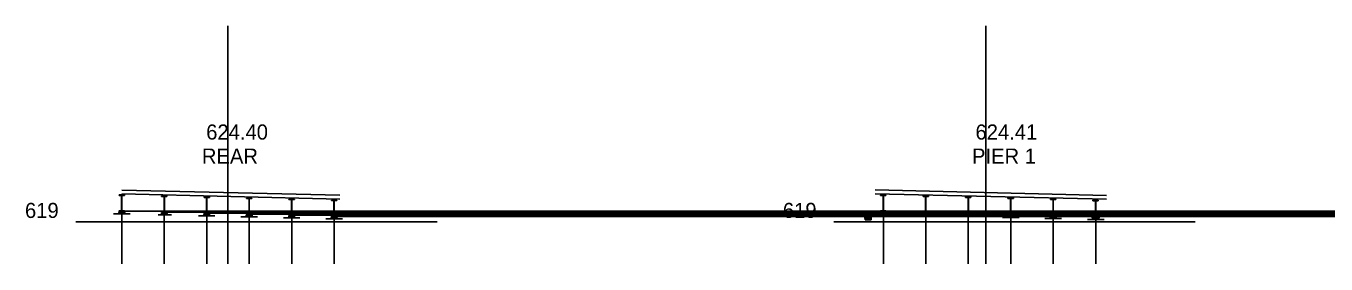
# Model space of a CAD drawing. Extents: x 2376379 to 2383101, y 559608 to 561720.
# Drawn here: x 2377257.5 to 2377498.6, y 560758 to 560802.1 of the extents above; entities that cross this region are included whole.
import ezdxf

# ---------------------------------------------------------------- set-up
doc = ezdxf.new("R2010")
doc.units = 0
for name, color, linetype in [('BR_X_SV_Abut', 7, 'Continuous'), ('DR_X_Ditch', 7, 'Continuous'), ('SV_X_Toe_of_Slope', 7, 'Continuous')]:
    doc.layers.add(name, color=color, linetype=linetype)

msp = doc.modelspace()

# ---------------------------------------------------------------- linework, layer by layer
at = {"layer": 'BR_X_SV_Abut'}
for p, q in [((2377413.12, 560766.61), (2377413.12, 560766.41)), ((2377414.29, 560766.61), (2377413.12, 560766.61)), ((2377414.29, 560766.41), (2377413.12, 560766.41)), ((2377413.16, 560766.41), (2377413.16, 560766.12)), ((2377414.25, 560766.12), (2377413.16, 560766.12)), ((2377414.25, 560766.41), (2377414.25, 560766.12)), ((2377414.29, 560766.61), (2377414.29, 560766.41))]:
    msp.add_line(p, q, dxfattribs=at)
at = {"layer": 'DR_X_Ditch'}
for p, q in [((2377274.81, 560770.75), (2377275.81, 560770.75)), ((2377274.81, 560770.75), (2377274.81, 560770.66)), ((2377274.81, 560770.66), (2377275.81, 560770.66)), ((2377275.28, 560767.83), (2377275.28, 560770.66)), ((2377275.33, 560767.83), (2377275.33, 560770.66)), ((2377275.81, 560770.75), (2377275.81, 560770.66)), ((2377282.69, 560770.56), (2377283.69, 560770.56)), ((2377282.69, 560770.56), (2377282.69, 560770.47)), ((2377282.69, 560770.47), (2377283.69, 560770.47)), ((2377283.16, 560767.64), (2377283.16, 560770.47)), ((2377283.21, 560767.64), (2377283.21, 560770.47)), ((2377283.69, 560770.56), (2377283.69, 560770.47)), ((2377290.56, 560770.38), (2377291.56, 560770.38)), ((2377290.56, 560770.38), (2377290.56, 560770.29)), ((2377290.56, 560770.29), (2377291.56, 560770.29)), ((2377291.03, 560767.46), (2377291.03, 560770.29)), ((2377291.08, 560767.46), (2377291.08, 560770.29)), ((2377291.56, 560770.38), (2377291.56, 560770.29)), ((2377298.43, 560770.16), (2377299.43, 560770.16)), ((2377298.43, 560770.16), (2377298.43, 560770.07)), ((2377299.43, 560770.16), (2377299.43, 560770.07)), ((2377416.01, 560770.74), (2377417.01, 560770.74)), ((2377416.01, 560770.74), (2377416.01, 560770.65)), ((2377416.01, 560770.74), (2377417.01, 560770.74)), ((2377416.01, 560770.65), (2377417.01, 560770.65)), ((2377416.08, 560770.77), (2377416.95, 560770.77)), ((2377416.08, 560770.77), (2377416.08, 560770.74)), ((2377416.49, 560767.82), (2377416.49, 560770.65)), ((2377416.54, 560767.82), (2377416.54, 560770.65)), ((2377416.95, 560770.77), (2377416.95, 560770.74)), ((2377417.01, 560770.74), (2377417.01, 560770.65)), ((2377423.89, 560770.57), (2377424.89, 560770.57)), ((2377423.89, 560770.57), (2377423.89, 560770.48)), ((2377423.89, 560770.57), (2377424.89, 560770.57)), ((2377423.89, 560770.48), (2377424.89, 560770.48)), ((2377423.96, 560770.6), (2377424.83, 560770.6)), ((2377423.96, 560770.6), (2377423.96, 560770.57)), ((2377424.37, 560767.65), (2377424.37, 560770.48)), ((2377424.42, 560767.65), (2377424.42, 560770.48)), ((2377424.83, 560770.6), (2377424.83, 560770.57)), ((2377424.89, 560770.57), (2377424.89, 560770.48)), ((2377431.76, 560770.39), (2377432.76, 560770.39)), ((2377431.76, 560770.39), (2377431.76, 560770.3)), ((2377431.76, 560770.39), (2377432.76, 560770.39)), ((2377431.76, 560770.3), (2377432.76, 560770.3)), ((2377431.83, 560770.42), (2377432.7, 560770.42)), ((2377431.83, 560770.42), (2377431.83, 560770.39)), ((2377432.24, 560767.47), (2377432.24, 560770.3)), ((2377432.29, 560767.47), (2377432.29, 560770.3)), ((2377432.7, 560770.42), (2377432.7, 560770.39)), ((2377432.76, 560770.39), (2377432.76, 560770.3)), ((2377439.64, 560770.19), (2377440.64, 560770.19)), ((2377439.64, 560770.19), (2377439.64, 560770.1)), ((2377439.64, 560770.19), (2377440.64, 560770.19)), ((2377439.71, 560770.22), (2377440.58, 560770.22)), ((2377439.71, 560770.22), (2377439.71, 560770.19)), ((2377440.58, 560770.22), (2377440.58, 560770.19)), ((2377440.64, 560770.19), (2377440.64, 560770.1)), ((2377274.81, 560767.83), (2377275.81, 560767.83)), ((2377274.81, 560767.83), (2377274.81, 560767.75)), ((2377274.81, 560767.75), (2377275.81, 560767.75)), ((2377275.81, 560767.75), (2377275.81, 560767.83)), ((2377298.43, 560770.07), (2377299.43, 560770.07)), ((2377298.9, 560767.24), (2377298.9, 560770.07)), ((2377298.95, 560767.24), (2377298.95, 560770.07)), ((2377306.31, 560770), (2377307.31, 560770)), ((2377306.31, 560770), (2377306.31, 560769.91)), ((2377306.31, 560769.91), (2377307.31, 560769.91)), ((2377306.78, 560767.08), (2377306.78, 560769.91)), ((2377306.83, 560767.08), (2377306.83, 560769.91)), ((2377307.31, 560770), (2377307.31, 560769.91)), ((2377314.18, 560769.8), (2377315.18, 560769.8)), ((2377314.18, 560769.8), (2377314.18, 560769.71)), ((2377314.18, 560769.71), (2377315.18, 560769.71)), ((2377314.65, 560766.88), (2377314.65, 560769.71)), ((2377314.7, 560766.88), (2377314.7, 560769.71)), ((2377315.18, 560769.8), (2377315.18, 560769.71)), ((2377415.95, 560767.74), (2377416.01, 560767.74)), ((2377415.95, 560767.74), (2377415.95, 560767.65)), ((2377416.01, 560767.82), (2377417.01, 560767.82)), ((2377416.01, 560767.82), (2377416.01, 560767.74)), ((2377416.01, 560767.74), (2377417.01, 560767.74)), ((2377417.01, 560767.74), (2377417.01, 560767.82)), ((2377417.01, 560767.74), (2377417.08, 560767.74)), ((2377417.08, 560767.74), (2377417.08, 560767.65)), ((2377439.64, 560770.1), (2377440.64, 560770.1)), ((2377440.12, 560767.27), (2377440.12, 560770.1)), ((2377440.17, 560767.27), (2377440.17, 560770.1)), ((2377447.51, 560769.99), (2377448.51, 560769.99)), ((2377447.51, 560769.99), (2377447.51, 560769.9)), ((2377447.51, 560769.99), (2377448.51, 560769.99)), ((2377447.51, 560769.9), (2377448.51, 560769.9)), ((2377447.58, 560770.02), (2377448.45, 560770.02)), ((2377447.58, 560770.02), (2377447.58, 560769.99)), ((2377447.99, 560767.07), (2377447.99, 560769.9)), ((2377448.04, 560767.07), (2377448.04, 560769.9)), ((2377448.45, 560770.02), (2377448.45, 560769.99)), ((2377448.51, 560769.99), (2377448.51, 560769.9)), ((2377455.39, 560769.77), (2377456.39, 560769.77)), ((2377455.39, 560769.77), (2377455.39, 560769.68)), ((2377455.39, 560769.77), (2377456.39, 560769.77)), ((2377455.39, 560769.68), (2377456.39, 560769.68)), ((2377455.46, 560769.8), (2377456.33, 560769.8)), ((2377455.46, 560769.8), (2377455.46, 560769.77)), ((2377455.87, 560766.85), (2377455.87, 560769.68)), ((2377455.92, 560766.85), (2377455.92, 560769.68)), ((2377456.33, 560769.8), (2377456.33, 560769.77)), ((2377456.39, 560769.77), (2377456.39, 560769.68)), ((2377282.69, 560767.64), (2377283.69, 560767.64)), ((2377282.69, 560767.64), (2377282.69, 560767.56)), ((2377282.69, 560767.56), (2377283.69, 560767.56)), ((2377283.69, 560767.56), (2377283.69, 560767.64)), ((2377290.56, 560767.46), (2377291.56, 560767.46)), ((2377290.56, 560767.46), (2377290.56, 560767.38)), ((2377290.56, 560767.38), (2377291.56, 560767.38)), ((2377291.56, 560767.38), (2377291.56, 560767.46)), ((2377298.43, 560767.24), (2377299.43, 560767.24)), ((2377298.43, 560767.24), (2377298.43, 560767.16)), ((2377298.43, 560767.16), (2377299.43, 560767.16)), ((2377299.43, 560767.16), (2377299.43, 560767.24)), ((2377306.31, 560767.08), (2377307.31, 560767.08)), ((2377306.31, 560767.08), (2377306.31, 560767)), ((2377306.31, 560767), (2377307.31, 560767)), ((2377307.31, 560767), (2377307.31, 560767.08)), ((2377314.18, 560766.88), (2377315.18, 560766.88)), ((2377314.18, 560766.88), (2377314.18, 560766.8)), ((2377314.18, 560766.8), (2377315.18, 560766.8)), ((2377315.18, 560766.8), (2377315.18, 560766.88)), ((2377415.95, 560767.69), (2377417.08, 560767.69)), ((2377415.95, 560767.65), (2377417.08, 560767.65)), ((2377423.83, 560767.57), (2377423.89, 560767.57)), ((2377423.83, 560767.57), (2377423.83, 560767.48)), ((2377423.83, 560767.52), (2377424.96, 560767.52)), ((2377423.83, 560767.48), (2377424.96, 560767.48)), ((2377423.89, 560767.65), (2377424.89, 560767.65)), ((2377423.89, 560767.65), (2377423.89, 560767.57)), ((2377423.89, 560767.57), (2377424.89, 560767.57)), ((2377424.89, 560767.57), (2377424.89, 560767.65)), ((2377424.89, 560767.57), (2377424.96, 560767.57)), ((2377424.96, 560767.57), (2377424.96, 560767.48)), ((2377431.7, 560767.39), (2377431.76, 560767.39)), ((2377431.7, 560767.39), (2377431.7, 560767.3)), ((2377431.7, 560767.34), (2377432.83, 560767.34)), ((2377431.7, 560767.3), (2377432.83, 560767.3)), ((2377431.76, 560767.47), (2377432.76, 560767.47)), ((2377431.76, 560767.47), (2377431.76, 560767.39)), ((2377431.76, 560767.39), (2377432.76, 560767.39)), ((2377432.76, 560767.39), (2377432.76, 560767.47)), ((2377432.76, 560767.39), (2377432.83, 560767.39)), ((2377432.83, 560767.39), (2377432.83, 560767.3)), ((2377439.58, 560767.19), (2377439.64, 560767.19)), ((2377439.58, 560767.19), (2377439.58, 560767.1)), ((2377439.58, 560767.14), (2377440.71, 560767.14)), ((2377439.58, 560767.1), (2377440.71, 560767.1)), ((2377439.64, 560767.27), (2377440.64, 560767.27)), ((2377439.64, 560767.27), (2377439.64, 560767.19)), ((2377439.64, 560767.19), (2377440.64, 560767.19)), ((2377440.64, 560767.19), (2377440.64, 560767.27)), ((2377440.64, 560767.19), (2377440.71, 560767.19)), ((2377440.71, 560767.19), (2377440.71, 560767.1)), ((2377447.45, 560766.99), (2377447.51, 560766.99)), ((2377447.45, 560766.99), (2377447.45, 560766.9)), ((2377447.45, 560766.94), (2377448.58, 560766.94)), ((2377447.45, 560766.9), (2377448.58, 560766.9)), ((2377447.51, 560767.07), (2377448.51, 560767.07)), ((2377447.51, 560767.07), (2377447.51, 560766.99)), ((2377447.51, 560766.99), (2377448.51, 560766.99)), ((2377448.51, 560766.99), (2377448.51, 560767.07)), ((2377448.51, 560766.99), (2377448.58, 560766.99)), ((2377448.58, 560766.99), (2377448.58, 560766.9)), ((2377455.33, 560766.77), (2377455.39, 560766.77)), ((2377455.33, 560766.77), (2377455.33, 560766.68)), ((2377455.33, 560766.72), (2377456.46, 560766.72)), ((2377455.33, 560766.68), (2377456.46, 560766.68)), ((2377455.39, 560766.85), (2377456.39, 560766.85)), ((2377455.39, 560766.85), (2377455.39, 560766.77)), ((2377455.39, 560766.77), (2377456.39, 560766.77)), ((2377456.39, 560766.77), (2377456.39, 560766.85)), ((2377456.39, 560766.77), (2377456.46, 560766.77)), ((2377456.46, 560766.77), (2377456.46, 560766.68))]:
    msp.add_line(p, q, dxfattribs=at)
at = {"layer": 'SV_X_Toe_of_Slope'}
for p, q in [((2377294.96, 560802.07), (2377294.96, 560757.96)), ((2377435.5, 560802.07), (2377435.5, 560757.96)), ((2377275.31, 560771.67), (2377315.74, 560770.7)), ((2377275.31, 560770.96), (2377315.74, 560769.99)), ((2377275.31, 560770.75), (2377275.31, 560770.91)), ((2377283.19, 560770.56), (2377283.19, 560770.72)), ((2377291.06, 560770.38), (2377291.06, 560770.54)), ((2377298.93, 560770.16), (2377298.93, 560770.32)), ((2377306.81, 560770), (2377306.81, 560770.16)), ((2377415, 560771.7), (2377457.92, 560770.67)), ((2377415, 560770.99), (2377457.92, 560769.96)), ((2377416.51, 560770.77), (2377416.51, 560770.94)), ((2377424.39, 560770.6), (2377424.39, 560770.77)), ((2377432.26, 560770.42), (2377432.26, 560770.59)), ((2377440.14, 560770.22), (2377440.14, 560770.39)), ((2377448.01, 560770.02), (2377448.01, 560770.19)), ((2377274.77, 560767.75), (2377275.85, 560767.75)), ((2377641.92, 560767.73), (2377275.85, 560767.73)), ((2377314.68, 560769.8), (2377314.68, 560769.96)), ((2377455.89, 560769.8), (2377455.89, 560769.97)), ((2377455.89, 560769.8), (2377455.89, 560769.97)), ((2377266.78, 560765.8), (2377333.8, 560765.8)), ((2377273.77, 560767.27), (2377276.84, 560767.27)), ((2377274.77, 560767.62), (2377274.77, 560767.5)), ((2377274.77, 560767.5), (2377275.85, 560767.5)), ((2377274.81, 560767.5), (2377274.81, 560767.27)), ((2377275.31, 560767.27), (2377275.31, 560757.96)), ((2377275.81, 560767.5), (2377275.81, 560767.27)), ((2377275.85, 560767.62), (2377275.85, 560767.5)), ((2377282.03, 560767.08), (2377284.53, 560767.08)), ((2377282.65, 560767.56), (2377283.73, 560767.56)), ((2377282.65, 560767.43), (2377282.65, 560767.31)), ((2377282.65, 560767.31), (2377283.73, 560767.31)), ((2377282.69, 560767.31), (2377282.69, 560767.08)), ((2377283.19, 560767.08), (2377283.19, 560757.96)), ((2377283.69, 560767.31), (2377283.69, 560767.08)), ((2377649.79, 560767.56), (2377283.73, 560767.56)), ((2377283.73, 560767.43), (2377283.73, 560767.31)), ((2377289.52, 560766.9), (2377292.59, 560766.9)), ((2377290.52, 560767.38), (2377291.6, 560767.38)), ((2377290.52, 560767.25), (2377290.52, 560767.13)), ((2377290.52, 560767.13), (2377291.6, 560767.13)), ((2377290.56, 560767.13), (2377290.56, 560766.9)), ((2377291.06, 560766.9), (2377291.06, 560757.96)), ((2377291.56, 560767.13), (2377291.56, 560766.9)), ((2377657.66, 560767.38), (2377291.6, 560767.38)), ((2377291.6, 560767.25), (2377291.6, 560767.13)), ((2377297.39, 560766.68), (2377300.46, 560766.68)), ((2377298.39, 560767.16), (2377299.47, 560767.16)), ((2377298.39, 560767.03), (2377298.39, 560766.91)), ((2377298.39, 560766.91), (2377299.47, 560766.91)), ((2377298.43, 560766.91), (2377298.43, 560766.68)), ((2377298.93, 560766.68), (2377298.93, 560757.96)), ((2377299.43, 560766.91), (2377299.43, 560766.68)), ((2377299.47, 560767.03), (2377299.47, 560766.91)), ((2377665.58, 560767.22), (2377299.48, 560767.22)), ((2377305.27, 560766.52), (2377308.34, 560766.52)), ((2377306.27, 560767), (2377307.35, 560767)), ((2377306.27, 560766.87), (2377306.27, 560766.75)), ((2377306.27, 560766.75), (2377307.35, 560766.75)), ((2377306.31, 560766.75), (2377306.31, 560766.52)), ((2377306.81, 560766.52), (2377306.81, 560757.96)), ((2377307.31, 560766.75), (2377307.31, 560766.52)), ((2377673.41, 560766.98), (2377307.35, 560766.98)), ((2377307.35, 560766.87), (2377307.35, 560766.75)), ((2377313.14, 560766.32), (2377316.21, 560766.32)), ((2377314.14, 560766.8), (2377315.22, 560766.8)), ((2377314.14, 560766.67), (2377314.14, 560766.55)), ((2377314.14, 560766.55), (2377315.22, 560766.55)), ((2377314.18, 560766.55), (2377314.18, 560766.32)), ((2377314.68, 560766.32), (2377314.68, 560757.96)), ((2377315.18, 560766.55), (2377315.18, 560766.32)), ((2377315.22, 560766.67), (2377315.22, 560766.55)), ((2377681.29, 560766.77), (2377315.23, 560766.77)), ((2377407.32, 560765.8), (2377474.35, 560765.8)), ((2377415, 560767.15), (2377418.07, 560767.15)), ((2377415.87, 560767.65), (2377417.16, 560767.65)), ((2377415.87, 560767.57), (2377415.87, 560767.44)), ((2377415.87, 560767.44), (2377417.16, 560767.44)), ((2377415.99, 560767.44), (2377415.99, 560767.15)), ((2377416.53, 560767.15), (2377416.53, 560757.96)), ((2377417.07, 560767.44), (2377417.07, 560767.15)), ((2377417.16, 560767.57), (2377417.16, 560767.44)), ((2377422.88, 560766.98), (2377425.95, 560766.98)), ((2377423.75, 560767.48), (2377425.04, 560767.48)), ((2377423.75, 560767.4), (2377423.75, 560767.27)), ((2377423.75, 560767.27), (2377425.04, 560767.27)), ((2377423.87, 560767.27), (2377423.87, 560766.98)), ((2377424.41, 560766.98), (2377424.41, 560757.96)), ((2377424.95, 560767.27), (2377424.95, 560766.98)), ((2377425.04, 560767.4), (2377425.04, 560767.27)), ((2377430.75, 560766.8), (2377433.82, 560766.8)), ((2377431.62, 560767.3), (2377432.91, 560767.3)), ((2377431.62, 560767.22), (2377431.62, 560767.09)), ((2377431.62, 560767.09), (2377432.91, 560767.09)), ((2377431.74, 560767.09), (2377431.74, 560766.8)), ((2377432.28, 560766.8), (2377432.28, 560757.96)), ((2377432.82, 560767.09), (2377432.82, 560766.8)), ((2377432.91, 560767.22), (2377432.91, 560767.09)), ((2377438.63, 560766.6), (2377441.7, 560766.6)), ((2377439.5, 560767.1), (2377440.79, 560767.1)), ((2377439.5, 560767.02), (2377439.5, 560766.89)), ((2377439.5, 560766.89), (2377440.79, 560766.89)), ((2377439.62, 560766.89), (2377439.62, 560766.6)), ((2377440.16, 560766.6), (2377440.16, 560757.96)), ((2377440.7, 560766.89), (2377440.7, 560766.6)), ((2377440.79, 560767.02), (2377440.79, 560766.89)), ((2377446.5, 560766.4), (2377449.57, 560766.4)), ((2377447.37, 560766.9), (2377448.66, 560766.9)), ((2377447.37, 560766.82), (2377447.37, 560766.69)), ((2377447.37, 560766.69), (2377448.66, 560766.69)), ((2377447.49, 560766.69), (2377447.49, 560766.4)), ((2377448.03, 560766.4), (2377448.03, 560757.96)), ((2377448.57, 560766.69), (2377448.57, 560766.4)), ((2377448.66, 560766.82), (2377448.66, 560766.69)), ((2377454.38, 560766.18), (2377457.45, 560766.18)), ((2377455.25, 560766.68), (2377456.54, 560766.68)), ((2377455.25, 560766.6), (2377455.25, 560766.47)), ((2377455.25, 560766.47), (2377456.54, 560766.47)), ((2377455.37, 560766.47), (2377455.37, 560766.18)), ((2377455.91, 560766.18), (2377455.91, 560757.96)), ((2377456.45, 560766.47), (2377456.45, 560766.18)), ((2377456.54, 560766.6), (2377456.54, 560766.47))]:
    msp.add_line(p, q, dxfattribs=at)

# ---------------------------------------------------------------- texts
for s, p in [('624.40', (2377290.96, 560781.02)), ('624.41', (2377433.61, 560781.02)), ('REAR', (2377290.16, 560776.56)), ('PIER 1', (2377432.96, 560776.56)), ('619', (2377257.36, 560766.49)), ('619', (2377397.9, 560766.49))]:
    msp.add_text(s, height=2.8, dxfattribs=at).set_placement(p)

doc.saveas('drawing.dxf')
